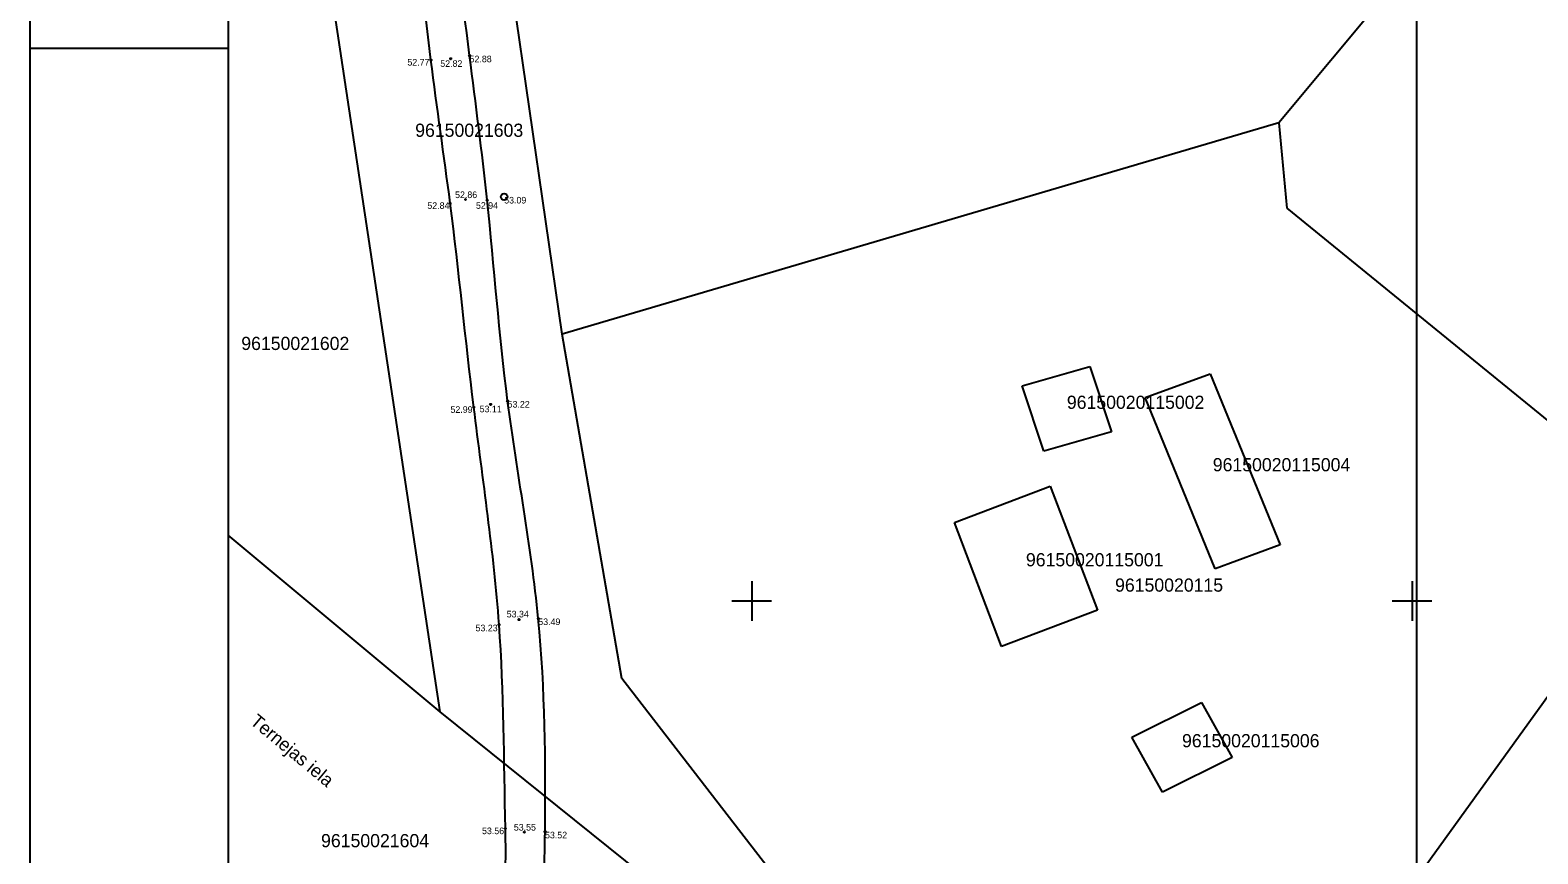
# Model space of a CAD drawing. Extents: x 578395 to 578590, y 418519 to 418816.
# Drawn here: x 578395.4 to 578509.5, y 418680.8 to 418743.2 of the extents above; entities that cross this region are included whole.
import ezdxf

# ---------------------------------------------------------------- set-up
doc = ezdxf.new("R2010")
doc.units = 0
for name, color, linetype in [('BUVE_EKAS_UZMR_####_#', 7, 'Continuous'), ('BUVE_EKAS_UZMR_TKST_#', 7, 'Continuous'), ('CELI_CMAL_####_####_#', 7, 'Continuous'), ('CELI_IELA_####_TKST_#', 7, 'Continuous'), ('GEOD_ELEM_####_####_#', 7, 'Continuous'), ('RAMI_PLAN_####_TKST_#', 7, 'Continuous'), ('RELJ_AATZ_####_TKST_#', 7, 'Continuous'), ('RELJ_ELEM_####_####_#', 7, 'Continuous'), ('ROBZ_PROJ_####_####_#', 7, 'Continuous'), ('ROBZ_PROJ_####_TKST_#', 7, 'Continuous'), ('ROBZ_UZMR_####_####_#', 7, 'Continuous'), ('ROBZ_UZMR_####_TKST_#', 7, 'Continuous'), ('SAKT_ELEM_####_####_#', 7, 'Continuous')]:
    doc.layers.add(name, color=color, linetype=linetype)

msp = doc.modelspace()

# ---------------------------------------------------------------- linework, layer by layer
at = {"layer": 'BUVE_EKAS_UZMR_####_#'}
for p, q in [((578470.48, 418716.29), (578475.59, 418717.76)), ((578475.59, 418717.76), (578477.24, 418712.81)), ((578479.8, 418715.4), (578484.72, 418717.2)), ((578484.72, 418717.2), (578490.01, 418704.24)), ((578472.12, 418711.35), (578470.48, 418716.29)), ((578485.09, 418702.43), (578479.8, 418715.4)), ((578477.24, 418712.81), (578472.12, 418711.35)), ((578465.34, 418705.94), (578472.6, 418708.7)), ((578472.6, 418708.7), (578476.17, 418699.31)), ((578468.91, 418696.54), (578465.34, 418705.94)), ((578490.01, 418704.24), (578485.09, 418702.43)), ((578476.17, 418699.31), (578468.91, 418696.54)), ((578478.79, 418689.69), (578484.06, 418692.31)), ((578484.06, 418692.31), (578486.37, 418688.14)), ((578481.09, 418685.52), (578478.79, 418689.69)), ((578486.37, 418688.14), (578481.09, 418685.52))]:
    msp.add_line(p, q, dxfattribs=at)
at = {"layer": 'CELI_CMAL_####_####_#'}
for points in [[(578428.55, 418677.14), (578430.48, 418675.63), (578430.57, 418675.83), (578431.34, 418682.76), (578430.86, 418698.21), (578428.95, 418714.66), (578427.16, 418730.13), (578425.7, 418740.98), (578424.08, 418754.82), (578421.62, 418770.83), (578419.54, 418786.89), (578417.73, 418801.98)], [(578540.02, 418586.37), (578525.99, 418597.85), (578512.59, 418608.64), (578501.67, 418618.24), (578486.37, 418629.74), (578473.85, 418639.53), (578461.4, 418649.85), (578445.48, 418664.31), (578434.89, 418671.62), (578433.59, 418673.24), (578433.71, 418674.57), (578434.34, 418682.51), (578433.83, 418698.67), (578431.51, 418715.15), (578429.96, 418730.38), (578428.63, 418741.31), (578426.86, 418755.17), (578424.46, 418771.37), (578422.35, 418787.38), (578420.6, 418802.68)]]:
    msp.add_spline(points, degree=3, dxfattribs=at)
at = {"layer": 'GEOD_ELEM_####_####_#'}
for p, q in [((578450, 418701.5), (578450, 418700)), ((578500, 418701.5), (578500, 418700)), ((578448.5, 418700), (578450, 418700)), ((578450, 418700), (578450, 418698.5)), ((578450, 418700), (578451.5, 418700)), ((578498.5, 418700), (578500, 418700)), ((578500, 418700), (578500, 418698.5)), ((578500, 418700), (578501.5, 418700))]:
    msp.add_line(p, q, dxfattribs=at)
at = {"layer": 'RAMI_PLAN_####_TKST_#'}
for p, q in [((578395.35, 418667.61), (578395.35, 418816.11)), ((578500.35, 418667.61), (578500.35, 418816.11)), ((578410.35, 418741.86), (578395.35, 418741.86))]:
    msp.add_line(p, q, dxfattribs=at)
msp.add_lwpolyline([(578410.35, 418811.11), (578410.35, 418524.11), (578585.35, 418524.11), (578585.35, 418811.11)], close=True, dxfattribs=at)
at = {"layer": 'RELJ_ELEM_####_####_#'}
for centre in [(578428.63, 418741.31), (578425.7, 418740.98), (578427.2, 418741.08), (578427.16, 418730.13), (578428.32, 418730.41), (578429.96, 418730.38), (578430.22, 418714.89), (578431.51, 418715.15), (578428.95, 418714.66), (578430.86, 418698.21), (578432.37, 418698.59), (578433.83, 418698.67), (578431.34, 418682.76), (578432.78, 418682.48), (578434.34, 418682.51)]:
    msp.add_circle(centre, 0.05, dxfattribs=at)
at = {"layer": 'ROBZ_PROJ_####_####_#'}
msp.add_line((578426.39, 418691.61), (578410.35, 418704.97), dxfattribs=at)
at = {"layer": 'ROBZ_UZMR_####_####_#'}
for p, q in [((578426.39, 418691.61), (578414.31, 418771.8)), ((578507.98, 418757.95), (578489.92, 418736.22)), ((578435.64, 418720.21), (578431.84, 418746.43)), ((578489.92, 418736.22), (578435.64, 418720.21)), ((578489.92, 418736.22), (578490.52, 418729.76)), ((578490.52, 418729.76), (578519.75, 418705.92)), ((578440.17, 418694.13), (578435.64, 418720.21)), ((578459.53, 418669.04), (578440.17, 418694.13)), ((578500.28, 418678.93), (578511.07, 418693.87)), ((578479.13, 418649.24), (578426.39, 418691.61))]:
    msp.add_line(p, q, dxfattribs=at)
at = {"layer": 'SAKT_ELEM_####_####_#'}
msp.add_circle((578431.25, 418730.61), 0.25, dxfattribs=at)

# ---------------------------------------------------------------- texts
at = {"layer": 'BUVE_EKAS_UZMR_TKST_#'}
for s, p in [('96150020115002', (578473.86, 418714.55)), ('96150020115004', (578484.91, 418709.82)), ('96150020115001', (578470.76, 418702.62)), ('96150020115006', (578482.58, 418688.91))]:
    msp.add_text(s, height=1, dxfattribs=at).set_placement(p)
at = {"layer": 'CELI_IELA_####_TKST_#'}
msp.add_text('Ternejas iela', height=1, rotation=320.1946, dxfattribs=at).set_placement((578411.94, 418690.74))
at = {"layer": 'RELJ_AATZ_####_TKST_#'}
for s, p in [('52.88', (578428.63, 418740.81)), ('52.77', (578423.92, 418740.56)), ('52.82', (578426.41, 418740.46)), ('52.86', (578427.53, 418730.52)), ('52.84', (578425.43, 418729.7)), ('52.94', (578429.11, 418729.71)), ('53.09', (578431.25, 418730.11)), ('53.22', (578431.51, 418714.65)), ('52.99', (578427.18, 418714.25)), ('53.11', (578429.39, 418714.29)), ('53.34', (578431.44, 418698.75)), ('53.23', (578429.08, 418697.7)), ('53.49', (578433.83, 418698.17)), ('53.55', (578431.98, 418682.6)), ('53.56', (578429.57, 418682.33)), ('53.52', (578434.34, 418682.01))]:
    msp.add_text(s, height=0.5, dxfattribs=at).set_placement(p)
at = {"layer": 'ROBZ_PROJ_####_TKST_#'}
for s, p in [('96150021602', (578411.34, 418719.01)), ('96150021604', (578417.38, 418681.34))]:
    msp.add_text(s, height=1, dxfattribs=at).set_placement(p)
at = {"layer": 'ROBZ_UZMR_####_TKST_#'}
for s, p in [('96150021603', (578424.51, 418735.16)), ('96150020115', (578477.51, 418700.7))]:
    msp.add_text(s, height=1, dxfattribs=at).set_placement(p)

doc.saveas('drawing.dxf')
